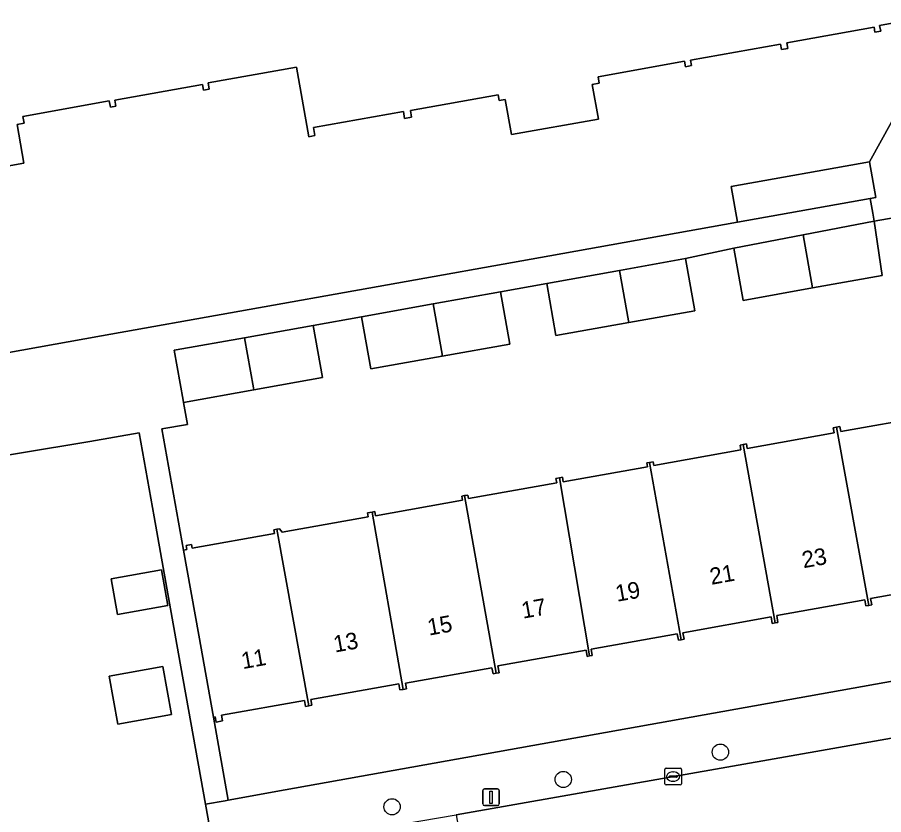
# Model space of a CAD drawing. Extents: x 157793 to 159380, y 380877 to 382313.
# Drawn here: x 158414.2 to 158466.2, y 381373.8 to 381421.8 of the extents above; entities that cross this region are included whole.
import ezdxf

# ---------------------------------------------------------------- set-up
doc = ezdxf.new("R2010")
doc.units = 0
for name, color, linetype in [('IMGEO_Boom', 7, 'Continuous'), ('IMGEO_Erf', 7, 'Continuous'), ('IMGEO_Kolk', 7, 'Continuous'), ('IMGEO_Lichtmast', 7, 'Continuous'), ('IMGEO_Pand', 7, 'Continuous'), ('IMGEO_Pand_nummerreeks', 7, 'Continuous'), ('IMGEO_Rijbaan_lokaal_open', 7, 'Continuous'), ('IMGEO_Voetpad_open', 7, 'Continuous')]:
    doc.layers.add(name, color=color, linetype=linetype)

msp = doc.modelspace()

# ---------------------------------------------------------------- linework, layer by layer
at = {"layer": 'IMGEO_Boom'}
for centre in [(158456.415, 381377.579), (158446.969, 381375.935), (158436.685, 381374.292)]:
    msp.add_circle(centre, 0.489, dxfattribs=at)
at = {"layer": 'IMGEO_Erf'}
for points in [[(158468.721, 381421.767), (158465.985, 381421.278), (158466.048, 381420.926), (158465.705, 381420.865), (158465.65, 381421.173), (158460.412, 381420.236), (158460.473, 381419.894), (158460.083, 381419.825), (158460.025, 381420.149), (158454.624, 381419.183), (158454.681, 381418.863), (158454.323, 381418.799), (158454.266, 381419.122), (158449.063, 381418.192), (158449.132, 381417.809), (158448.714, 381417.734), (158449.087, 381415.646), (158443.861, 381414.712), (158443.483, 381416.828), (158443.115, 381416.762), (158443.055, 381417.098), (158437.78, 381416.154), (158437.85, 381415.758), (158437.438, 381415.685), (158437.363, 381416.106), (158431.954, 381415.139), (158432.041, 381414.653), (158431.683, 381414.589), (158430.935, 381418.772), (158425.624, 381417.823), (158425.693, 381417.439), (158425.357, 381417.379), (158425.293, 381417.735), (158420.017, 381416.791), (158420.084, 381416.415), (158419.754, 381416.356), (158419.686, 381416.735), (158414.498, 381415.807), (158414.571, 381415.396), (158414.147, 381415.32), (158414.559, 381413.003), (158409.075, 381412.023)], [(158410.621, 381401.079), (158419.211, 381402.615), (158435.843, 381405.589), (158446.157, 381407.433), (158457.444, 381409.451), (158457.062, 381411.59), (158465.383, 381413.078), (158466.711, 381415.512)], [(158468.406, 381409.988), (158465.655, 381409.513), (158466.13, 381406.238), (158461.953, 381405.491), (158457.777, 381404.745), (158457.217, 381407.88), (158454.326, 381407.254), (158454.887, 381404.119), (158450.911, 381403.408), (158446.534, 381402.626), (158445.974, 381405.761), (158443.205, 381405.254), (158443.766, 381402.119), (158439.701, 381401.392), (158435.413, 381400.626), (158434.853, 381403.761), (158431.939, 381403.235), (158432.5, 381400.1), (158428.38, 381399.364), (158424.147, 381398.607), (158424.379, 381397.287), (158422.843, 381397.016), (158424.151, 381389.73), (158424.346, 381389.765), (158424.302, 381390.015), (158424.629, 381390.073), (158424.671, 381389.84), (158429.61, 381390.723), (158429.57, 381390.95), (158429.765, 381390.985), (158429.907, 381391.01), (158430.076, 381390.81), (158435.251, 381391.735), (158435.209, 381391.967), (158435.489, 381392.017), (158435.65, 381392.046), (158435.695, 381391.791), (158440.914, 381392.724), (158440.869, 381392.975), (158441.031, 381393.004), (158441.233, 381393.04), (158441.272, 381392.822), (158446.577, 381393.77), (158446.529, 381394.039), (158446.742, 381394.077), (158446.919, 381394.109), (158446.969, 381393.83), (158452.031, 381394.735), (158451.988, 381394.975), (158452.152, 381395.004), (158452.367, 381395.042), (158452.407, 381394.819), (158457.652, 381395.757), (158457.6, 381396.045), (158457.78, 381396.077), (158457.973, 381396.111), (158458.02, 381395.844), (158463.247, 381396.779), (158463.192, 381397.087), (158463.395, 381397.123), (158463.601, 381397.16), (158463.655, 381396.858), (158468.877, 381397.792)], [(158418.462, 381362.577), (158418.114, 381362.516), (158418.072, 381362.754), (158418.051, 381362.871), (158418.313, 381362.917), (158417.434, 381367.893), (158417.154, 381367.844), (158417.095, 381368.178), (158417.385, 381368.229), (158417.336, 381368.507), (158422.475, 381369.415), (158426.243, 381370.08), (158425.473, 381374.444), (158423.856, 381383.494), (158422.382, 381391.739), (158421.482, 381396.777), (158418.518, 381396.255), (158409.932, 381394.841)], [(158470.598, 381387.732), (158465.439, 381386.809), (158465.506, 381386.433), (158465.333, 381386.402), (158465.161, 381386.371), (158465.095, 381386.739), (158459.796, 381385.792), (158459.87, 381385.377), (158459.702, 381385.347), (158459.534, 381385.317), (158459.463, 381385.711), (158454.159, 381384.763), (158454.23, 381384.367), (158454.063, 381384.337), (158453.897, 381384.307), (158453.826, 381384.701), (158448.638, 381383.773), (158448.706, 381383.391), (158448.557, 381383.365), (158448.408, 381383.338), (158448.341, 381383.714), (158443.04, 381382.766), (158443.113, 381382.358), (158442.932, 381382.326), (158442.749, 381382.293), (158442.686, 381382.647), (158437.498, 381381.72), (158437.557, 381381.391), (158437.355, 381381.355), (158437.154, 381381.319), (158437.087, 381381.692), (158431.803, 381380.748), (158431.865, 381380.399), (158431.671, 381380.365), (158431.476, 381380.33), (158431.412, 381380.685), (158426.439, 381379.795), (158426.498, 381379.462), (158426.109, 381379.392), (158426.052, 381379.71), (158425.946, 381379.691), (158426.84, 381374.689), (158430.261, 381375.309), (158473.339, 381383.038)]]:
    msp.add_lwpolyline(points, dxfattribs=at)
for points in [[(158422.825, 381388.533), (158423.203, 381386.394), (158420.176, 381385.859), (158419.798, 381387.998)], [(158419.68, 381382.149), (158422.903, 381382.725), (158423.418, 381379.844), (158420.195, 381379.268)]]:
    msp.add_lwpolyline(points, close=True, dxfattribs=at)
at = {"layer": 'IMGEO_Kolk'}
for p, q in [((158453.073, 381375.682), (158453.073, 381376.534)), ((158453.148, 381376.608), (158454, 381376.608)), ((158454.074, 381376.534), (158454.074, 381375.682)), ((158453.332, 381376.102), (158453.332, 381376.114)), ((158453.77, 381376.065), (158453.372, 381376.065)), ((158453.375, 381376.151), (158453.773, 381376.151)), ((158453.561, 381376.388), (158453.586, 381376.388)), ((158453.816, 381376.114), (158453.816, 381376.102)), ((158454, 381375.608), (158453.148, 381375.608)), ((158453.584, 381375.828), (158453.559, 381375.828))]:
    msp.add_line(p, q, dxfattribs=at)
for points in [[(158453.073, 381375.682), (158453.073, 381376.534)], [(158453.148, 381376.608), (158454, 381376.608)], [(158454.074, 381376.534), (158454.074, 381375.682)], [(158454, 381375.608), (158453.148, 381375.608)]]:
    msp.add_lwpolyline(points, dxfattribs=at)
for centre, radius, start, end in [((158453.15, 381376.532), 0.0765, 91.552, 178.448), ((158453.15, 381376.532), 0.0765, 91.552, 178.448), ((158453.998, 381376.532), 0.0765, 1.552, 88.448), ((158453.998, 381376.532), 0.0765, 1.552, 88.448), ((158453.372, 381376.111), 0.0403, 85.8775, 175.7526), ((158453.369, 381376.101), 0.0366, 178.938, 274.7102), ((158453.773, 381376.108), 0.043, 264.8664, 352.4533), ((158453.777, 381376.113), 0.0386, 1.7309, 96.639), ((158453.15, 381375.684), 0.0765, 181.552, 268.448), ((158453.15, 381375.684), 0.0765, 181.552, 268.448), ((158453.998, 381375.684), 0.0765, 271.552, 358.448), ((158453.998, 381375.684), 0.0765, 271.552, 358.448)]:
    msp.add_arc(centre, radius, start, end, dxfattribs=at)
for centre, major_axis, ratio, start_param, end_param in [((158453.56, 381376.108), (-0.387, 0.002), 0.722429, 4.712389, 7.853982), ((158453.585, 381376.108), (-0.39, 0.002), 0.717154, 1.570796, 4.712389)]:
    msp.add_ellipse(centre, major_axis=major_axis, ratio=ratio, start_param=start_param, end_param=end_param, dxfattribs=at)
at = {"layer": 'IMGEO_Lichtmast'}
for p, q in [((158442.132, 381374.467), (158442.132, 381375.267)), ((158442.132, 381375.267), (158442.132, 381374.467)), ((158442.232, 381375.367), (158443.022, 381375.367)), ((158443.022, 381375.367), (158442.232, 381375.367)), ((158443.122, 381375.267), (158443.122, 381374.467)), ((158443.122, 381374.467), (158443.122, 381375.267)), ((158443.022, 381374.367), (158442.232, 381374.367)), ((158442.232, 381374.367), (158443.022, 381374.367))]:
    msp.add_line(p, q, dxfattribs=at)
msp.add_lwpolyline([(158442.552, 381375.242), (158442.702, 381375.242), (158442.702, 381374.492), (158442.552, 381374.492), (158442.552, 381375.242)], dxfattribs=at)
for centre, start, end in [((158442.232, 381375.267), 90, 180), ((158442.232, 381375.267), 90, 180), ((158443.022, 381375.267), 0, 90), ((158443.022, 381375.267), 360, 90), ((158442.232, 381374.467), 180, 270), ((158442.232, 381374.467), 180, 270), ((158443.022, 381374.467), 270, 0), ((158443.022, 381374.467), 270, 0)]:
    msp.add_arc(centre, 0.1, start, end, dxfattribs=at)
at = {"layer": 'IMGEO_Pand'}
msp.add_lwpolyline([(158409.075, 381412.023), (158414.559, 381413.003), (158414.147, 381415.32), (158414.571, 381415.396), (158414.498, 381415.807), (158419.686, 381416.735), (158419.754, 381416.356), (158420.084, 381416.415), (158420.017, 381416.791), (158425.293, 381417.735), (158425.357, 381417.379), (158425.693, 381417.439), (158425.624, 381417.823), (158430.935, 381418.772), (158431.683, 381414.589), (158432.041, 381414.653), (158431.954, 381415.139), (158437.363, 381416.106), (158437.438, 381415.685), (158437.85, 381415.758), (158437.78, 381416.154), (158443.055, 381417.098), (158443.115, 381416.762), (158443.483, 381416.828), (158443.861, 381414.712), (158449.087, 381415.646), (158448.714, 381417.734), (158449.132, 381417.809), (158449.063, 381418.192), (158454.266, 381419.122), (158454.323, 381418.799), (158454.681, 381418.863), (158454.624, 381419.183), (158460.025, 381420.149), (158460.083, 381419.825), (158460.473, 381419.894), (158460.412, 381420.236), (158465.65, 381421.173), (158465.705, 381420.865), (158466.048, 381420.926), (158465.985, 381421.278), (158468.721, 381421.767)], dxfattribs=at)
for points in [[(158465.765, 381410.939), (158465.383, 381413.078), (158457.062, 381411.59), (158457.444, 381409.451), (158465.425, 381410.878)], [(158461.383, 381408.686), (158461.953, 381405.491), (158466.13, 381406.238), (158465.655, 381409.513)], [(158461.383, 381408.686), (158457.217, 381407.88), (158457.777, 381404.745), (158461.953, 381405.491)], [(158450.911, 381403.408), (158454.887, 381404.119), (158454.326, 381407.254), (158450.353, 381406.544), (158450.895, 381403.515)], [(158450.911, 381403.408), (158450.895, 381403.515), (158450.353, 381406.544), (158445.974, 381405.761), (158446.534, 381402.626)], [(158439.701, 381401.392), (158443.766, 381402.119), (158443.205, 381405.254), (158439.143, 381404.528), (158439.683, 381401.508)], [(158439.701, 381401.392), (158439.683, 381401.508), (158439.143, 381404.528), (158434.853, 381403.761), (158435.413, 381400.626)], [(158428.38, 381399.364), (158432.5, 381400.1), (158431.939, 381403.235), (158427.821, 381402.499), (158428.361, 381399.481)], [(158428.38, 381399.364), (158428.361, 381399.481), (158427.821, 381402.499), (158423.709, 381401.764), (158423.587, 381401.742), (158424.122, 381398.749), (158424.147, 381398.607)], [(158463.395, 381397.123), (158465.333, 381386.402), (158465.506, 381386.433), (158465.439, 381386.809), (158470.598, 381387.732), (158470.656, 381387.407), (158471.091, 381387.485), (158471.168, 381387.698), (158469.29, 381398.205), (158468.818, 381398.121), (158468.877, 381397.792), (158463.655, 381396.858), (158463.601, 381397.16)], [(158463.395, 381397.123), (158463.192, 381397.087), (158463.247, 381396.779), (158458.02, 381395.844), (158457.973, 381396.111), (158457.78, 381396.077), (158459.702, 381385.347), (158459.87, 381385.377), (158459.796, 381385.792), (158465.095, 381386.739), (158465.161, 381386.371), (158465.333, 381386.402)], [(158457.78, 381396.077), (158457.6, 381396.045), (158457.652, 381395.757), (158452.407, 381394.819), (158452.367, 381395.042), (158452.152, 381395.004), (158454.063, 381384.337), (158454.23, 381384.367), (158454.159, 381384.763), (158459.463, 381385.711), (158459.534, 381385.317), (158459.702, 381385.347)], [(158448.557, 381383.365), (158448.706, 381383.391), (158448.638, 381383.773), (158453.826, 381384.701), (158453.897, 381384.307), (158454.063, 381384.337), (158452.152, 381395.004), (158451.988, 381394.975), (158452.031, 381394.735), (158446.969, 381393.83), (158446.919, 381394.109), (158446.742, 381394.077)], [(158448.557, 381383.365), (158446.742, 381394.077), (158446.529, 381394.039), (158446.577, 381393.77), (158441.272, 381392.822), (158441.233, 381393.04), (158441.031, 381393.004), (158442.932, 381382.326), (158443.113, 381382.358), (158443.04, 381382.766), (158448.341, 381383.714), (158448.408, 381383.338)], [(158437.355, 381381.355), (158437.557, 381381.391), (158437.498, 381381.72), (158442.686, 381382.647), (158442.749, 381382.293), (158442.932, 381382.326), (158441.031, 381393.004), (158440.869, 381392.975), (158440.914, 381392.724), (158435.695, 381391.791), (158435.65, 381392.046), (158435.489, 381392.017)], [(158429.765, 381390.985), (158431.671, 381380.365), (158431.865, 381380.399), (158431.803, 381380.748), (158437.087, 381381.692), (158437.154, 381381.319), (158437.355, 381381.355), (158435.489, 381392.017), (158435.209, 381391.967), (158435.251, 381391.735), (158430.076, 381390.81), (158429.907, 381391.01)], [(158429.765, 381390.985), (158429.57, 381390.95), (158429.61, 381390.723), (158424.671, 381389.84), (158424.629, 381390.073), (158424.302, 381390.015), (158424.346, 381389.765), (158424.151, 381389.73), (158425.066, 381384.613), (158425.946, 381379.691), (158426.052, 381379.71), (158426.109, 381379.392), (158426.498, 381379.462), (158426.439, 381379.795), (158431.412, 381380.685), (158431.476, 381380.33), (158431.671, 381380.365)], [(158422.825, 381388.533), (158419.798, 381387.998), (158420.176, 381385.859), (158423.203, 381386.394)], [(158419.68, 381382.149), (158420.195, 381379.268), (158423.418, 381379.844), (158422.903, 381382.725)]]:
    msp.add_lwpolyline(points, close=True, dxfattribs=at)
at = {"layer": 'IMGEO_Rijbaan_lokaal_open'}
msp.add_lwpolyline([(158505.213, 381385.172), (158504.063, 381384.916), (158476.602, 381380.158), (158440.528, 381373.814), (158445.193, 381347.236), (158445.222, 381347.098), (158445.233, 381347.012), (158446.688, 381338.314), (158447.454, 381334.427), (158452.57, 381335.311), (158451.692, 381340.294), (158450.847, 381345.084), (158450.524, 381346.918), (158449.648, 381351.886), (158449.222, 381354.283), (158448.428, 381358.713), (158447.508, 381363.857)], dxfattribs=at)
at = {"layer": 'IMGEO_Voetpad_open'}
for points in [[(158474.035, 381396.043), (158473.348, 381399.718), (158472.987, 381401.837), (158472.222, 381406.104), (158470.761, 381414.277), (158470.458, 381415.965), (158470.43, 381416.122), (158469.743, 381416.009), (158466.904, 381415.544), (158466.711, 381415.512), (158465.383, 381413.078), (158465.765, 381410.939), (158465.425, 381410.878), (158465.575, 381409.986), (158465.655, 381409.513), (158468.406, 381409.988), (158473.339, 381383.038), (158430.261, 381375.309), (158426.84, 381374.689), (158426.648, 381374.654), (158425.473, 381374.444), (158426.243, 381370.08)], [(158409.932, 381394.841), (158418.518, 381396.255), (158421.482, 381396.777), (158422.382, 381391.739), (158423.856, 381383.494), (158425.473, 381374.444), (158426.648, 381374.654), (158426.84, 381374.689), (158425.946, 381379.691), (158425.066, 381384.613), (158424.151, 381389.73), (158422.843, 381397.016), (158424.379, 381397.287), (158424.147, 381398.607), (158424.122, 381398.749), (158423.587, 381401.742), (158423.709, 381401.764), (158427.821, 381402.499), (158431.939, 381403.235), (158434.853, 381403.761), (158439.143, 381404.528), (158443.205, 381405.254), (158445.974, 381405.761), (158450.353, 381406.544), (158454.326, 381407.254), (158457.217, 381407.88), (158461.383, 381408.686), (158465.655, 381409.513), (158465.575, 381409.986), (158465.425, 381410.878), (158457.444, 381409.451), (158446.157, 381407.433), (158435.843, 381405.589), (158419.211, 381402.615), (158410.621, 381401.079)], [(158442.91, 381348.784), (158439.604, 381348.192), (158435.23, 381372.903), (158440.528, 381373.814), (158476.602, 381380.158)]]:
    msp.add_lwpolyline(points, dxfattribs=at)

# ---------------------------------------------------------------- texts
at = {"layer": 'IMGEO_Pand_nummerreeks'}
for s, p in [('23', (158461.41, 381388.637)), ('21', (158455.871, 381387.639)), ('19', (158450.2, 381386.619)), ('17', (158444.55, 381385.602)), ('15', (158438.901, 381384.584)), ('13', (158433.251, 381383.567)), ('11', (158427.713, 381382.57))]:
    msp.add_text(s, height=1, rotation=10.2077, dxfattribs=at).set_placement(p)

doc.saveas('drawing.dxf')
